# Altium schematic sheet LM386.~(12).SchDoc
size A4
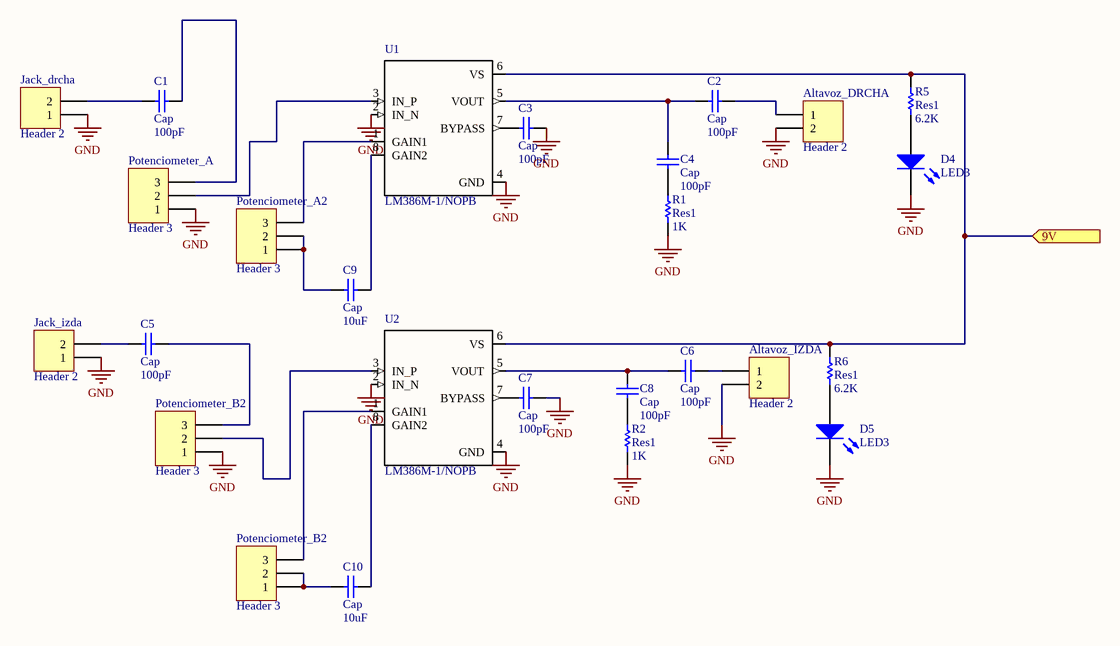
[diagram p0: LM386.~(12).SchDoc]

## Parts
(Parts that share a designator on the sheet are numbered #1, #2 ... from top to bottom, then left to right.)
Altavoz_DRCHA  Header 2  [HDR1X2]
Altavoz_IZDA  Header 2  [HDR1X2]
C1  Cap  value 100pF  [RAD-0.3]
C2  Cap  value 100pF  [RAD-0.3]
C3  Cap  value 100pF  [RAD-0.3]
C4  Cap  value 100pF  [RAD-0.3]
C5  Cap  value 100pF  [RAD-0.3]
C6  Cap  value 100pF  [RAD-0.3]
C7  Cap  value 100pF  [RAD-0.3]
C8  Cap  value 100pF  [RAD-0.3]
C9  Cap  value 10uF  [RAD-0.3]
C10  Cap  value 10uF  [RAD-0.3]
D4  LED3  [3.5X2.8X1.9]
D5  LED3  [3.5X2.8X1.9]
Jack_drcha  Header 2  [HDR1X2]
Jack_izda  Header 2  [HDR1X2]
Potenciometer_A  Header 3  [HDR1X3]
Potenciometer_A2  Header 3  [HDR1X3]
Potenciometer_B2#1  Header 3  [HDR1X3]
Potenciometer_B2#2  Header 3  [HDR1X3]
R1  Res1  value 1K  [AXIAL-0.3]
R2  Res1  value 1K  [AXIAL-0.3]
R5  Res1  value 6.2K  [AXIAL-0.3]
R6  Res1  value 6.2K  [AXIAL-0.3]
U1  LM386M-1/NOPB  [SOIC127P600X175-8N]
U2  LM386M-1/NOPB  [SOIC127P600X175-8N]

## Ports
9V (in)

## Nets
GND: Altavoz_DRCHA.2 Altavoz_IZDA.2 C3.1 C7.2 D4.2(K) D5.2(K) Jack_drcha.1 Jack_izda.1 Potenciometer_A.1 Potenciometer_B2#1.1 R1.1 R2.1 U1.2(IN_N) U1.4(GND) U2.2(IN_N) U2.4(GND)
9V: R5.1 R6.1 U1.6(VS) U2.6(VS) ; port 9V
NetAltavoz_DRCHA_1: Altavoz_DRCHA.1 C2.2
NetAltavoz_IZDA_1: Altavoz_IZDA.1 C6.2
NetC1_1: C1.1 Potenciometer_A.3
NetC1_2: C1.2 Jack_drcha.2
NetC2_1: C2.1 C4.2 U1.5(VOUT)
NetC3_2: C3.2 U1.7(BYPASS)
NetC4_1: C4.1 R1.2
NetC5_1: C5.1 Potenciometer_B2#1.3
NetC5_2: C5.2 Jack_izda.2
NetC6_1: C6.1 C8.2 U2.5(VOUT)
NetC7_1: C7.1 U2.7(BYPASS)
NetC8_1: C8.1 R2.2
NetC9_1: C9.1 U1.8(GAIN2)
NetC9_2: C9.2 Potenciometer_A2.1 Potenciometer_A2.2
NetC10_1: C10.1 U2.8(GAIN2)
NetC10_2: C10.2 Potenciometer_B2#2.1 Potenciometer_B2#2.2
NetD4_1: D4.1(A) R5.2
NetD5_1: D5.1(A) R6.2
NetPotenciometer_A2_3: Potenciometer_A2.3 U1.1(GAIN1)
NetPotenciometer_A_2: Potenciometer_A.2 U1.3(IN_P)
NetPotenciometer_B2#1_2: Potenciometer_B2#1.2 U2.3(IN_P)
NetPotenciometer_B2#2_3: Potenciometer_B2#2.3 U2.1(GAIN1)

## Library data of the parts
Altavoz_DRCHA Altavoz_IZDA Jack_drcha Jack_izda = Header 2: Header, 2-Pin
C1-C10 = Cap: Capacitor
D4 D5 = LED3: Typical BLUE SiC LED
Potenciometer_A Potenciometer_A2 Potenciometer_B2#1 Potenciometer_B2#2 = Header 3: Header, 3-Pin
R1 R2 R5 R6 = Res1: Resistor
U1 U2 = LM386M-1/NOPB: Wide Input Voltage Low Power Audio Amplifier with Internal Gain 8-SOIC 0 to 70; MF: Texas Instruments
